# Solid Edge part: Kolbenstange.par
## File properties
Username: ahadarics
Dokumentum tartalom típus: 0
Author: ahadarics
Last saved by: ahadarics
Revision: 83
Sűrűség: 0,000 kg/m^3
Pontosság: 0,990
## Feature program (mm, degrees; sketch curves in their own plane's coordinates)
base feature "unnamed BaseFeature 1"
thread "unnamed Thread 1"
chamfer "Letörés_1" setback 0.7
sketch for "Kihúzás_1" plane through (43.75, 0, 0) normal (1, 0, 0) x-axis (0, -1, 0)
  circle centre (0, 0) radius 10
extrude "Kihúzás_1" add finite 16 along -normal
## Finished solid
Body 1: solid body, 13 faces, 23 edges, 12 vertices.
  Faces by surface: plane 9, cylinder 3, cone 1
  Edges by curve: line 12, circle 11
Bounding box of the edges (mm): 202.500 x 20.000 x 20.000, from (-158.75, -10, -10) to (43.75, 10, 10).
Cylindrical faces by radius (mm): R4 x2, R10 x1
Conical faces (half-angle, radius in mm at the cone's reference point): 45 deg R3.3 x1
Planar faces by outward normal: +x 3, +z 1, -x 4, -z 1
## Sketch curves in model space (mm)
circle centre (43.75, 0, 0) radius 10
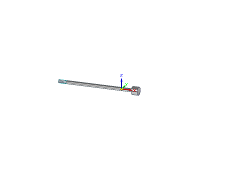
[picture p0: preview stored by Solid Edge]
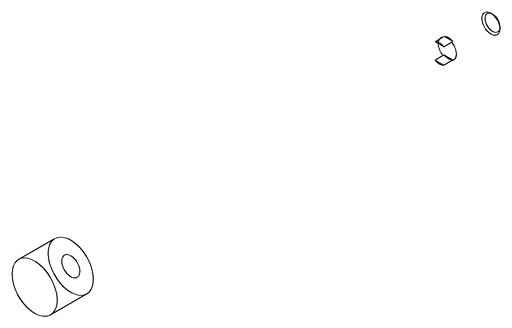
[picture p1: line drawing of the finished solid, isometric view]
